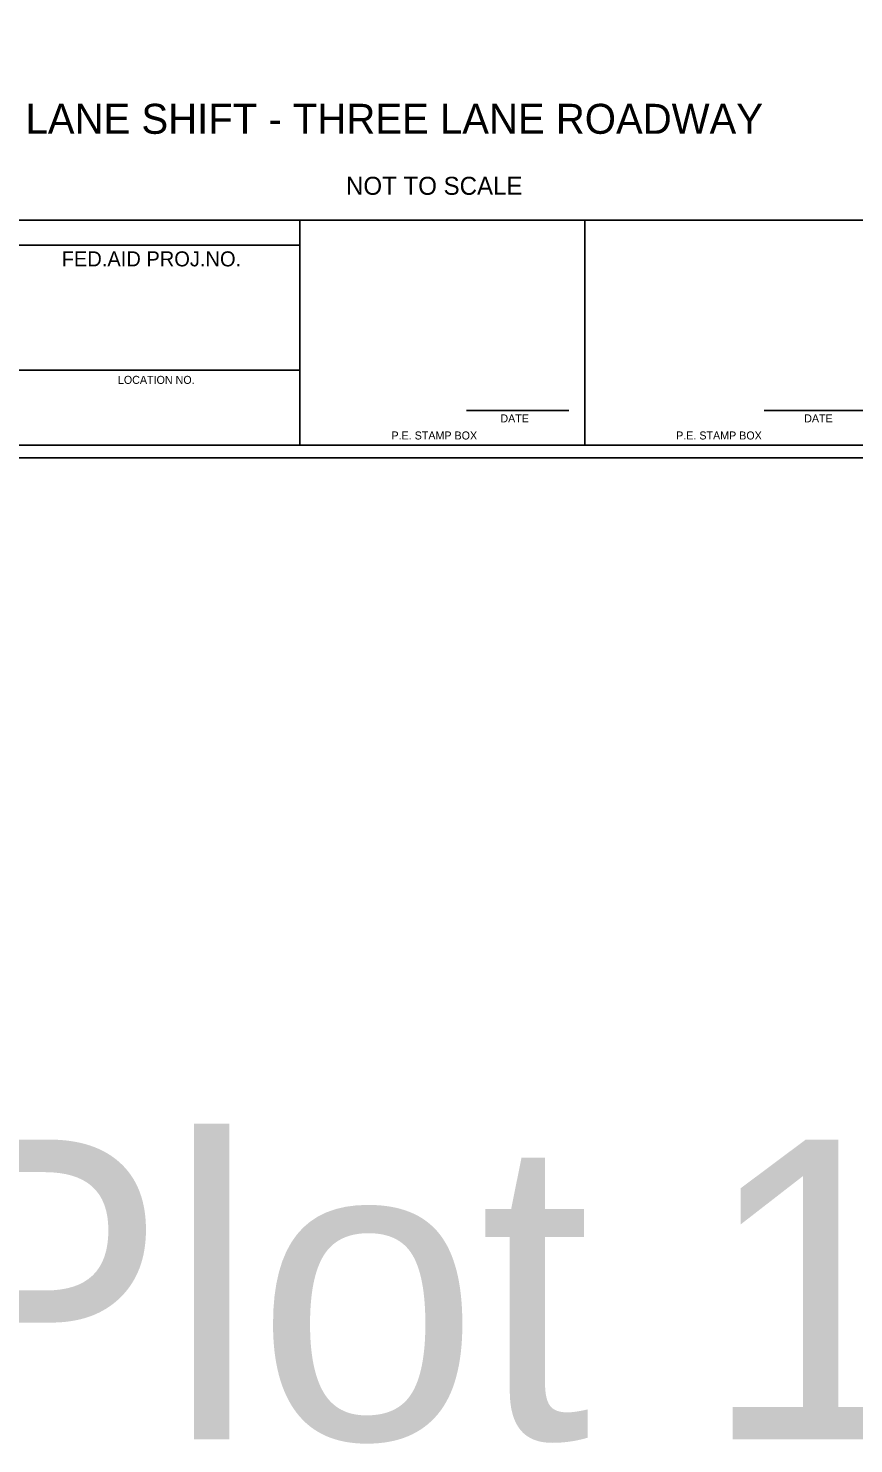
# Model space of a CAD drawing. Extents: x 99988 to 100172, y 99995 to 100047.
# Drawn here: x 100006.1 to 100010.23, y 99995.01 to 100002.09 of the extents above; entities that cross this region are included whole.
import ezdxf

# ---------------------------------------------------------------- set-up
doc = ezdxf.new("R2010")
doc.units = 0
for name, color, linetype in [('SH_DE_DetailHeading1Text', 7, 'Continuous'), ('SH_DE_DetailHeading3Text', 7, 'Continuous'), ('SH_GI_PlotLimits', 7, 'Continuous'), ('SH_GI_SheetBorder', 7, 'Continuous'), ('SH_GI_SheetLocationText', 7, 'Continuous'), ('SH_GI_SheetTextInCells', 7, 'Continuous')]:
    doc.layers.add(name, color=color, linetype=linetype)

msp = doc.modelspace()

# ---------------------------------------------------------------- linework, layer by layer
at = {"layer": 'SH_GI_PlotLimits'}
msp.add_lwpolyline([(99999.3125, 99999.9375), (100015.8125, 99999.9375), (100015.8125, 100010.4375), (99999.3125, 100010.4375)], close=True, dxfattribs=at)
at = {"layer": 'SH_GI_SheetBorder'}
for p, q in [((100000, 100001.1259), (100015.75, 100001.1259)), ((100007.4566, 100000), (100007.4566, 100001.1259)), ((100008.8828, 100000), (100008.8828, 100001.1259)), ((100000, 100001.0008), (100007.4566, 100001.0008)), ((100007.4566, 100000.3753), (100005.4466, 100000.3753)), ((100008.2903, 100000.1733), (100008.802, 100000.1733)), ((100009.7797, 100000.1733), (100010.2914, 100000.1733)), ((100000, 100000), (100015.75, 100000))]:
    msp.add_line(p, q, dxfattribs=at)

# ---------------------------------------------------------------- texts
at = {"layer": 'SH_DE_DetailHeading1Text'}
msp.add_text('LANE SHIFT - THREE LANE ROADWAY', height=0.15, dxfattribs=at).set_placement((100006.0844, 100001.5576))
at = {"layer": 'SH_DE_DetailHeading3Text'}
msp.add_text('NOT TO SCALE', height=0.09, dxfattribs=at).set_placement((100007.6876, 100001.2525))
at = {"layer": 'SH_GI_SheetLocationText'}
msp.add_text('Plot 1', height=1.5, dxfattribs=at).set_placement((100005.4547, 99995.0267))
at = {"layer": 'SH_GI_SheetTextInCells'}
for s, height, p in [('FED.AID PROJ.NO.', 0.07506, (100006.2652, 100000.8945)), ('LOCATION NO.', 0.040032, (100006.5465, 100000.3067)), ('DATE', 0.04003, (100008.4597, 100000.1141)), ('DATE', 0.04003, (100009.9794, 100000.1141)), ('P.E. STAMP BOX', 0.040032, (100007.915, 100000.0286)), ('P.E. STAMP BOX', 0.040032, (100009.339, 100000.0286))]:
    msp.add_text(s, height=height, dxfattribs=at).set_placement(p)

doc.saveas('drawing.dxf')
